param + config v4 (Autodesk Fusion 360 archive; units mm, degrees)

design "param + config"
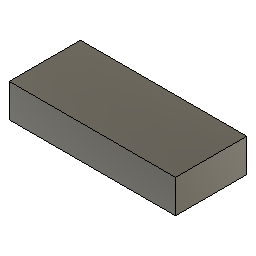
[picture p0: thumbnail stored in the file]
part number: brut conf 1
parameter "longueur" = 210
parameter "largeur" = 90
parameter "hauteurext" = 42
parameter "dlamage" = 10
sketch "Esquisse1" plane through (0, 0, 0) normal (0, 0, 1) x axis (1, 0, 0)
  line L1 (-105, -45) -> (105, -45)
  line L2 (-105, 45) -> (-105, -45)
  line L3 (105, 45) -> (-105, 45)
  line L4 (105, -45) -> (105, 45)
  line L5 (-105, 45) -> (105, -45)
  line L6 (105, 45) -> (-105, -45)
  point P6 (0, 0)
  point P1 (0, 0)
  point P4 (-105, 45)
  point P5 (105, 45)
  point P3 (-105, -45)
  horizontal L1
  perpendicular L1 L2
  parallel L1 L3
  parallel L2 L4
  coincident L5 P6
  coincident L6 P6
  coincident P1 P6
  dimension "d3" distance P4 P5 = 210 (= "longueur")
  dimension "d4" distance P3 P4 = 90 (= "largeur")
extrude "Extrusion" new body sketch "Esquisse1" profile of L1 L2 L3 L4 along normal blind 42 (= "hauteurext") named "hauteur"
sketch "Esquisse2" plane through (0, 0, 42) normal (0, 0, 1) x axis (-1, 0, 0)
  line L1 (105, -45) -> (-105, -45)
  line L2 (105, 45) -> (105, -45)
  point P2 (85, -25)
  dimension "d8" distance P2 L1 = 20
  dimension "d9" distance P2 L2 = 20
  dimension "d12" R-Pattern1-uDistance = -42.5 (= "-( longueur - 40 mm ) / ( nb_de_trous - 1 )")
  dimension "d13" R-Pattern1-vDistance = 33.3333 (= "( largeur - 40 mm ) / ( floor(nb_de_trous) / 2 - 1 )")
hole "Perçage1" HoleDiameter 5 (= "dlamage / 2") CBDepth 8.4 (= "hauteurext / 5") CBDiameter 10 (= "dlamage") named "dlam"
hole "Perçage2" HoleDiameter 5 (= "dlamage / 2") CBDepth 8.4 (= "hauteurext / 5") CBDiameter 10 (= "dlamage")
hole "Perçage3" HoleDiameter 5 (= "dlamage / 2") CBDepth 8.4 (= "hauteurext / 5") CBDiameter 10 (= "dlamage")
